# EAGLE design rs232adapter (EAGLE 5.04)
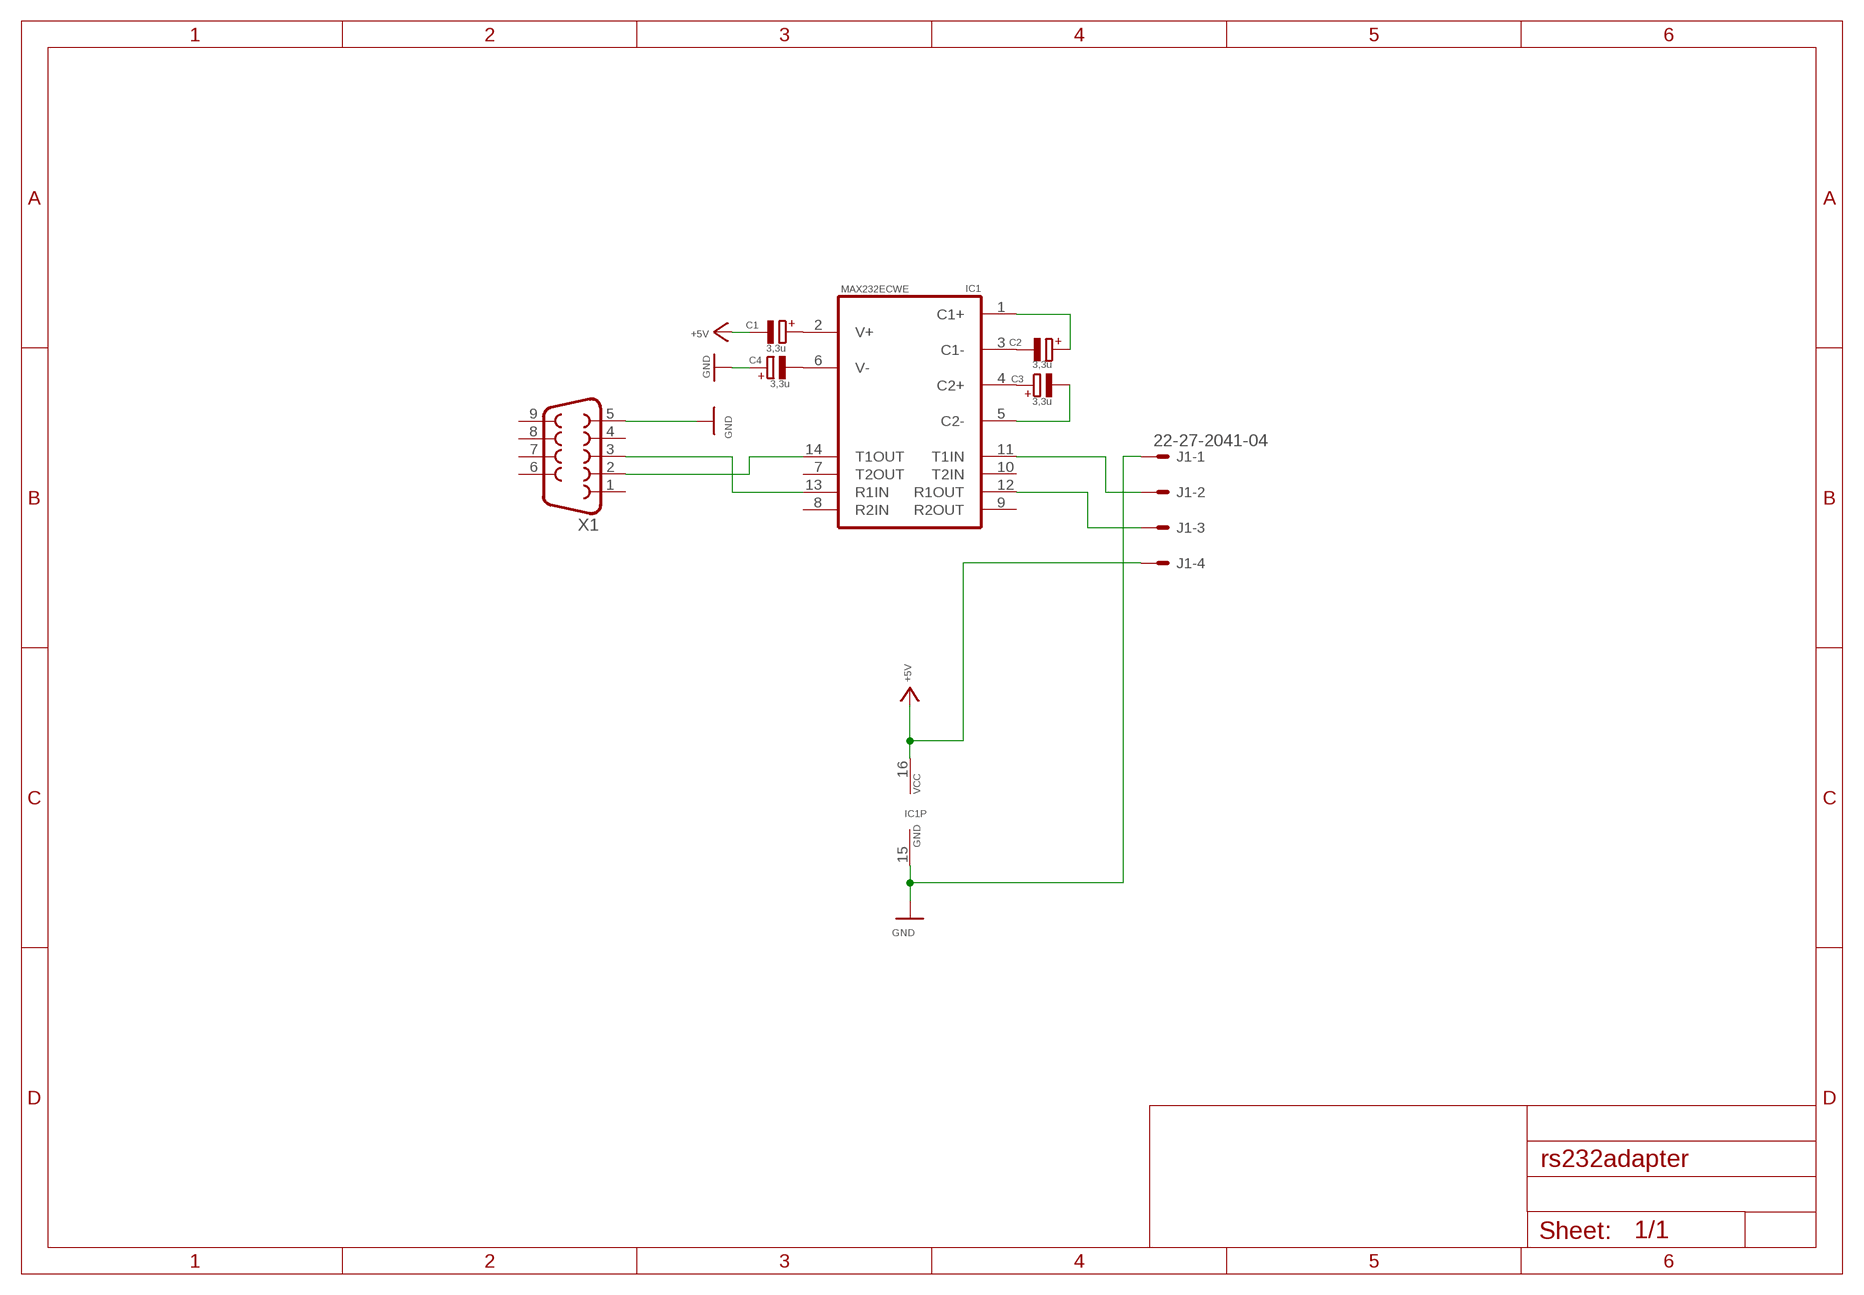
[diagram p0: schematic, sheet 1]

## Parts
C1  3,3u  CPOL-EUSMCB  [SMC_B]
C2  3,3u  CPOL-EUSMCB  [SMC_B]
C3  3,3u  CPOL-EUSMCB  [SMC_B]
C4  3,3u  CPOL-EUSMCB  [SMC_B]
IC1  MAX232ECWE  [SO16L]
J1  22-27-2041-04  [6410-04]
X1  F09D  [F09D]

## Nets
+5V: C1.- IC1.16(VCC) J1.4
GND: C4.+ IC1.15(GND) J1.1 X1.5
N$1: IC1.14(T1OUT) X1.2
N$2: IC1.13(R1IN) X1.3
N$3: IC1.11(T1IN) J1.2
N$4: IC1.12(R1OUT) J1.3
N$114: C2.+ IC1.1(C1+)
N$115: C3.- IC1.5(C2-)
N$116: C4.- IC1.6(V-)
N$117: C1.+ IC1.2(V+)
N$118: C2.- IC1.3(C1-)
N$119: C3.+ IC1.4(C2+)
Unconnected: IC1.7(T2OUT) IC1.8(R2IN) IC1.9(R2OUT) IC1.10(T2IN) X1.1 X1.4 X1.6 X1.7 X1.8 X1.9

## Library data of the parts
C1-C4 = rcl:CPOL-EU: POLARIZED CAPACITOR, European symbol
IC1 = maxim:MAX232ECWE: RS232 TRANSEIVER
J1 = con-molex:22-?-04: CONNECTOR wire to board 2.54 mm (.1 inch) pitch header
X1 = con-subd:F09: SUB-D

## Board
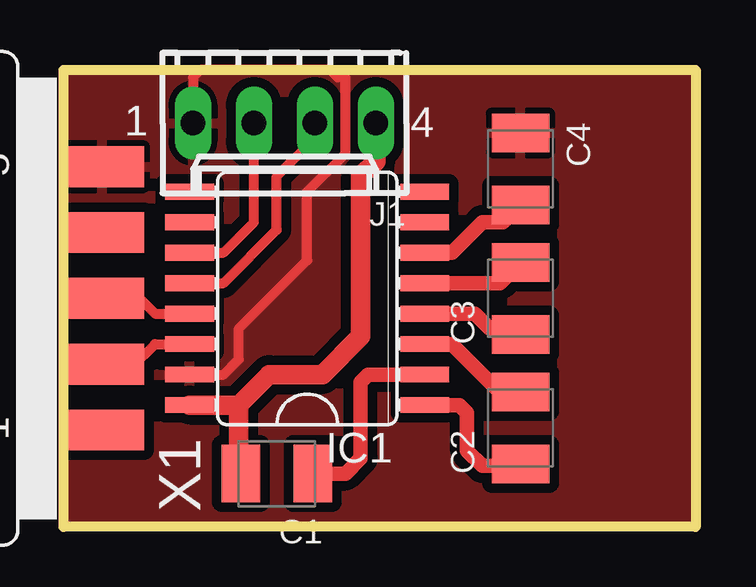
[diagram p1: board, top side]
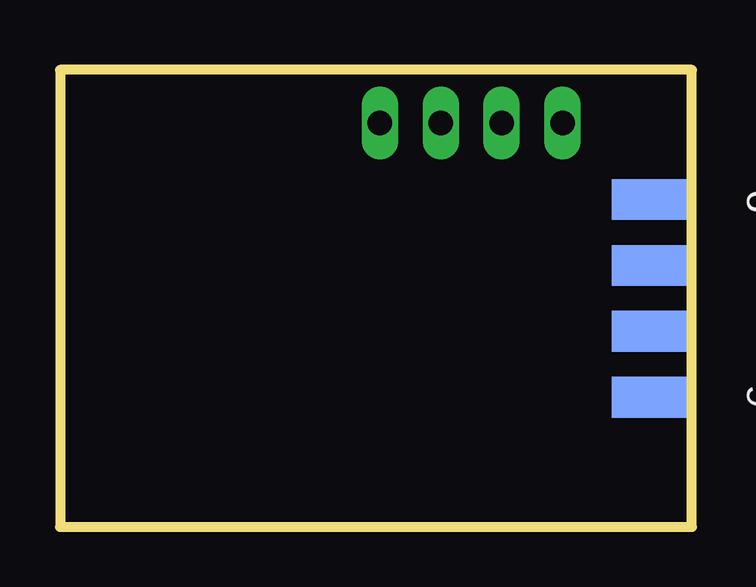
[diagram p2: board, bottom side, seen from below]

Size 26.35 x 19.05 mm. Coordinates in mm from the lower left corner, seen from the top.
Outline: 0,19.05 26.35,19.05 26.35,0 0,0 0,19.05
Copper layers (1*16): Top 0.035mm / dielectric 1.5mm / Bottom 0.035mm
Design rules "default *": minimum track width 10mil, minimum drill 24mil, track to track 8mil, track to pad 8mil, pad to pad 8mil, via to via 8mil, smd to smd 8mil, copper to edge 0mil, drill to drill 8mil, minimum pad ring 10mil, minimum via ring 8mil, stop-mask expansion 4mil, vias tented up to drill 0mil, thermal gap 10mil

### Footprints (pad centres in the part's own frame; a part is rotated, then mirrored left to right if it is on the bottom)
SMC_B = smd 1.6 x 2.4: + -1.5,0; - 1.5,0
SO16L = smd 0.66 x 2.032: 1 -4.445,-4.902; 2 -3.175,-4.902; 3 -1.905,-4.902; 4 -0.635,-4.902; 5 0.635,-4.902; 6 1.905,-4.902; 7 3.175,-4.902; 8 4.445,-4.902; 9 4.445,4.902; 10 3.175,4.902; 11 1.905,4.902; 12 0.635,4.902; 13 -0.635,4.902; 14 -1.905,4.902; 15 -3.175,4.902; 16 -4.445,4.902
6410-04 = drill 1.016 long: 1 3.81,0; 2 1.27,0; 3 -1.27,0; 4 -3.81,0
F09D = smd 1.7 x 3.5: 1 -5.486,-6.045; 2 -2.743,-6.045; 3 0,-6.045; 4 2.743,-6.045; 5 5.486,-6.045 | smd 1.7 x 3.5 bottom: 6 -4.115,-6.045; 7 -1.372,-6.045; 8 1.372,-6.045; 9 4.115,-6.045

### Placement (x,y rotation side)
C1  8.89,2.22 180 top
C2  19.05,4.13 90 top
C3  19.05,9.53 90 top
C4  19.05,14.92 270 top
IC1  10.16,9.53 90 top
J1  9.21,16.83 180 top
X1  -4.45,9.53 90 top

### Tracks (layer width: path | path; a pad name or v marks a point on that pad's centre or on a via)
+5V
  Top 0.813: J1.4 13.02,15.24 12.38,14.6 12.38,7.94 10.8,6.35 8.57,6.35 7.3,5.08 | 7.3,5.08 7.3,2.31 C1.- | IC1.16 7.3,5.08
GND
  Top 0.406: IC1.15 6.67,6.35 7.3,6.98 7.3,8.25 10.16,11.11 10.16,13.97 11.75,15.56 11.75,18.73 11.43,18.73 11.11,19.05 5.71,19.05 5.4,18.73 J1.1
  pour Top (isolate 0.406): 0,0 0,19.05 26.35,19.05 26.35,0
N$1
  Top 0.406: IC1.14 3.81,7.62 2.86,6.67 1.71,6.67 X1.2
N$2
  Top 0.406: IC1.13 3.81,8.89 3.18,9.53 X1.3
N$3
  Top 0.406: IC1.11 6.67,11.43 7.94,12.7 J1.2
N$4
  Top 0.406: IC1.12 6.67,10.16 8.89,12.38 8.89,14.6 10.48,16.19 J1.3
N$114
  Top 0.61: IC1.1 16.51,5.08 16.83,4.76 16.83,3.17 17.46,2.54 18.96,2.54 C2.+
N$115
  Top 0.61: IC1.5 18.18,10.16 C3.-
N$116
  Top 0.61: IC1.6 16.19,11.43 17.46,12.7 18.33,12.7 C4.-
N$117
  Top 0.61: IC1.2 12.7,6.35 12.38,6.03 12.38,2.86 11.75,2.22 C1.+
N$118
  Top 0.61: IC1.3 16.19,7.62 18.1,5.72 18.96,5.72 C2.-
N$119
  Top 0.61: IC1.4 17.14,8.89 17.78,8.25 18.82,8.25 C3.+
